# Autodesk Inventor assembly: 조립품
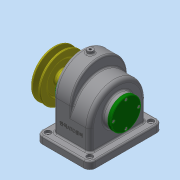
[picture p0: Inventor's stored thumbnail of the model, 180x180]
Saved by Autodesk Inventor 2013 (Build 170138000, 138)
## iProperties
Created: 2017-11
Part Number: 조립품
Document SubType Name: Assembly
Designer: dgall
Author: dgall
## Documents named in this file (14)
- C:\Users\dgall\Desktop\471007V1011\조립품.iam
- C:\Users\dgall\Desktop\471007V1011\본체.ipt
- C:\Users\dgall\Desktop\471007V1011\뒤커버.ipt
- C:\Users\dgall\Desktop\471007V1011\앞커버.ipt
- C:\Users\dgall\Desktop\471007V1011\축.ipt
- C:\Users\dgall\Desktop\471007V1011\베어링 6002.ipt
- C:\Users\dgall\Desktop\471007V1011\스퍼기어.ipt
- C:\Users\dgall\Desktop\471007V1011\키 - 6 x 6 x 22.ipt
- C:\Users\dgall\Desktop\471007V1011\오일 실 15 30 7.ipt
- C:\Users\dgall\Desktop\471007V1011\볼트 M3 x 8.ipt
- C:\Users\dgall\Desktop\471007V1011\V-벨트풀리.ipt
- C:\Users\dgall\Desktop\471007V1011\멈춤나사 - M4 x 10.ipt
- 멈춤나사 - M4 x 10.ipt
- C:\Users\dgall\Desktop\471007V1011\키 - 5 x 5 x 18.ipt
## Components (1 placed, 1 different names)
1. V-벨트풀리:1
